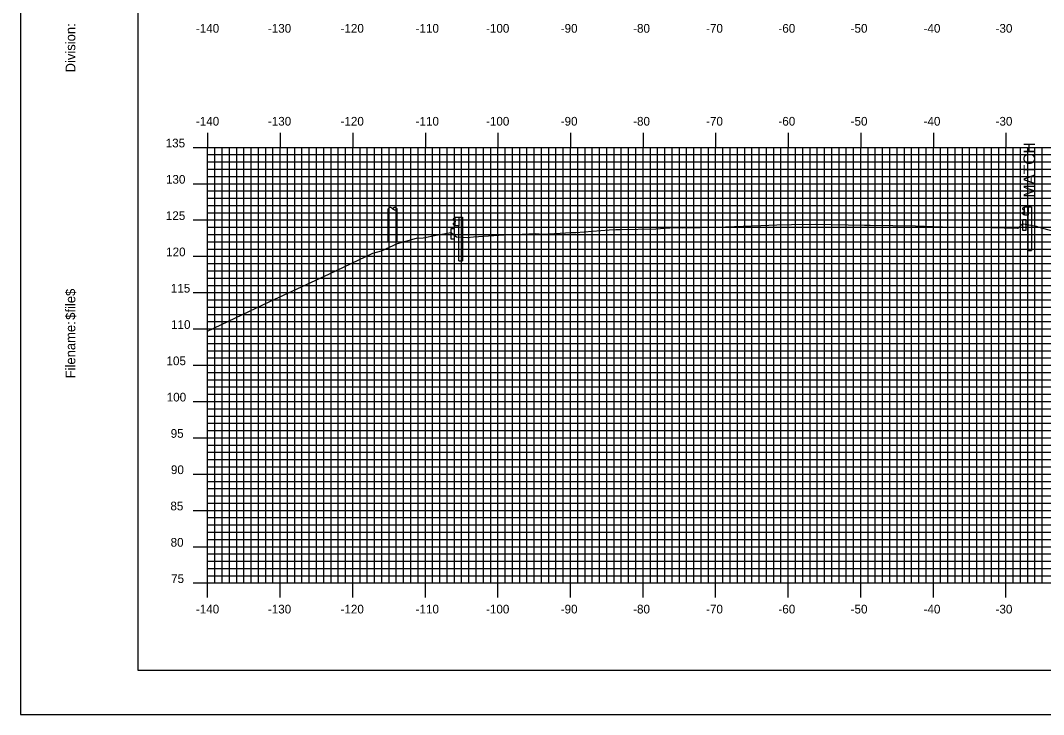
# Model space of a CAD drawing. Extents: x 857265 to 857608, y 364366 to 364586.
# Drawn here: x 857264.5 to 857405.5, y 364365.7 to 364461.3 of the extents above; entities that cross this region are included whole.
import ezdxf

# ---------------------------------------------------------------- set-up
doc = ezdxf.new("R2010")
doc.units = 0
for name, color, linetype in [('ANNOTATION', 7, 'Continuous'), ('BORDER', 7, 'Continuous'), ('H_V ANNOTATION', 7, 'Continuous'), ('M_Roadway_Centerline', 7, 'Continuous'), ('MAJOR', 7, 'Continuous'), ('MINOR', 7, 'Continuous'), ('PLOT BOUNDARY', 7, 'Continuous'), ('S_Curb_Type_1', 7, 'Continuous'), ('S_Guardrail_Beam', 7, 'Continuous'), ('S_Roadway_Centerline', 7, 'Continuous'), ('S_Utilities_Pole_Power', 7, 'Continuous')]:
    doc.layers.add(name, color=color, linetype=linetype)

msp = doc.modelspace()

# ---------------------------------------------------------------- linework, layer by layer
at = {"layer": 'BORDER'}
msp.add_lwpolyline([(857280.74, 364371.79), (857600.74, 364371.79), (857600.74, 364581.79), (857280.74, 364581.79)], close=True, dxfattribs=at)
at = {"layer": 'MAJOR'}
for p, q in [((857290.34, 364445.79), (857290.34, 364443.79)), ((857300.34, 364445.79), (857300.34, 364443.79)), ((857310.34, 364445.79), (857310.34, 364443.79)), ((857320.34, 364445.79), (857320.34, 364443.79)), ((857330.34, 364445.79), (857330.34, 364443.79)), ((857340.34, 364445.79), (857340.34, 364443.79)), ((857350.34, 364445.79), (857350.34, 364443.79)), ((857360.34, 364445.79), (857360.34, 364443.79)), ((857370.34, 364445.79), (857370.34, 364443.79)), ((857380.34, 364445.79), (857380.34, 364443.79)), ((857390.34, 364445.79), (857390.34, 364443.79)), ((857400.34, 364445.79), (857400.34, 364443.79)), ((857288.33, 364443.79), (857290.34, 364443.79)), ((857290.34, 364443.79), (857570.34, 364443.79)), ((857290.34, 364383.79), (857290.34, 364443.79)), ((857290.34, 364383.79), (857290.34, 364443.79)), ((857290.34, 364443.79), (857570.34, 364443.79)), ((857300.34, 364383.79), (857300.34, 364443.79)), ((857310.34, 364383.79), (857310.34, 364443.79)), ((857320.34, 364383.79), (857320.34, 364443.79)), ((857330.34, 364383.79), (857330.34, 364443.79)), ((857340.34, 364383.79), (857340.34, 364443.79)), ((857350.34, 364383.79), (857350.34, 364443.79)), ((857360.34, 364383.79), (857360.34, 364443.79)), ((857370.34, 364383.79), (857370.34, 364443.79)), ((857380.34, 364383.79), (857380.34, 364443.79)), ((857390.34, 364383.79), (857390.34, 364443.79)), ((857400.34, 364383.79), (857400.34, 364443.79)), ((857288.33, 364438.79), (857290.34, 364438.79)), ((857290.34, 364438.79), (857570.34, 364438.79)), ((857288.33, 364433.79), (857290.34, 364433.79)), ((857290.34, 364433.79), (857570.34, 364433.79)), ((857288.33, 364428.79), (857290.34, 364428.79)), ((857290.34, 364428.79), (857570.34, 364428.79)), ((857288.33, 364423.79), (857290.34, 364423.79)), ((857290.34, 364423.79), (857570.34, 364423.79)), ((857288.33, 364418.79), (857290.34, 364418.79)), ((857290.34, 364418.79), (857570.34, 364418.79)), ((857288.33, 364413.79), (857290.34, 364413.79)), ((857290.34, 364413.79), (857570.34, 364413.79)), ((857288.33, 364408.79), (857290.34, 364408.79)), ((857290.34, 364408.79), (857570.34, 364408.79)), ((857288.33, 364403.79), (857290.34, 364403.79)), ((857290.34, 364403.79), (857570.34, 364403.79)), ((857288.33, 364398.79), (857290.34, 364398.79)), ((857290.34, 364398.79), (857570.34, 364398.79)), ((857288.33, 364393.79), (857290.34, 364393.79)), ((857290.34, 364393.79), (857570.34, 364393.79)), ((857288.33, 364388.79), (857290.34, 364388.79)), ((857290.34, 364388.79), (857570.34, 364388.79)), ((857288.33, 364383.79), (857290.34, 364383.79)), ((857290.34, 364383.79), (857570.34, 364383.79)), ((857290.34, 364383.79), (857570.34, 364383.79)), ((857290.34, 364381.78), (857290.34, 364383.79)), ((857300.34, 364381.78), (857300.34, 364383.79)), ((857310.34, 364381.78), (857310.34, 364383.79)), ((857320.34, 364381.78), (857320.34, 364383.79)), ((857330.34, 364381.78), (857330.34, 364383.79)), ((857340.34, 364381.78), (857340.34, 364383.79)), ((857350.34, 364381.78), (857350.34, 364383.79)), ((857360.34, 364381.78), (857360.34, 364383.79)), ((857370.34, 364381.78), (857370.34, 364383.79)), ((857380.34, 364381.78), (857380.34, 364383.79)), ((857390.34, 364381.78), (857390.34, 364383.79)), ((857400.34, 364381.78), (857400.34, 364383.79))]:
    msp.add_line(p, q, dxfattribs=at)
at = {"layer": 'MINOR'}
for p, q in [((857291.34, 364383.79), (857291.34, 364443.79)), ((857292.34, 364383.79), (857292.34, 364443.79)), ((857293.34, 364383.79), (857293.34, 364443.79)), ((857294.34, 364383.79), (857294.34, 364443.79)), ((857295.34, 364383.79), (857295.34, 364443.79)), ((857296.34, 364383.79), (857296.34, 364443.79)), ((857297.34, 364383.79), (857297.34, 364443.79)), ((857298.34, 364383.79), (857298.34, 364443.79)), ((857299.34, 364383.79), (857299.34, 364443.79)), ((857301.34, 364383.79), (857301.34, 364443.79)), ((857302.34, 364383.79), (857302.34, 364443.79)), ((857303.34, 364383.79), (857303.34, 364443.79)), ((857304.34, 364383.79), (857304.34, 364443.79)), ((857305.34, 364383.79), (857305.34, 364443.79)), ((857306.34, 364383.79), (857306.34, 364443.79)), ((857307.34, 364383.79), (857307.34, 364443.79)), ((857308.34, 364383.79), (857308.34, 364443.79)), ((857309.34, 364383.79), (857309.34, 364443.79)), ((857311.34, 364383.79), (857311.34, 364443.79)), ((857312.34, 364383.79), (857312.34, 364443.79)), ((857313.34, 364383.79), (857313.34, 364443.79)), ((857314.34, 364383.79), (857314.34, 364443.79)), ((857315.34, 364383.79), (857315.34, 364443.79)), ((857316.34, 364383.79), (857316.34, 364443.79)), ((857317.34, 364383.79), (857317.34, 364443.79)), ((857318.34, 364383.79), (857318.34, 364443.79)), ((857319.34, 364383.79), (857319.34, 364443.79)), ((857321.34, 364383.79), (857321.34, 364443.79)), ((857322.34, 364383.79), (857322.34, 364443.79)), ((857323.34, 364383.79), (857323.34, 364443.79)), ((857324.34, 364383.79), (857324.34, 364443.79)), ((857325.34, 364383.79), (857325.34, 364443.79)), ((857326.34, 364383.79), (857326.34, 364443.79)), ((857327.34, 364383.79), (857327.34, 364443.79)), ((857328.34, 364383.79), (857328.34, 364443.79)), ((857329.34, 364383.79), (857329.34, 364443.79)), ((857331.34, 364383.79), (857331.34, 364443.79)), ((857332.34, 364383.79), (857332.34, 364443.79)), ((857333.34, 364383.79), (857333.34, 364443.79)), ((857334.34, 364383.79), (857334.34, 364443.79)), ((857335.34, 364383.79), (857335.34, 364443.79)), ((857336.34, 364383.79), (857336.34, 364443.79)), ((857337.34, 364383.79), (857337.34, 364443.79)), ((857338.34, 364383.79), (857338.34, 364443.79)), ((857339.34, 364383.79), (857339.34, 364443.79)), ((857341.34, 364383.79), (857341.34, 364443.79)), ((857342.34, 364383.79), (857342.34, 364443.79)), ((857343.34, 364383.79), (857343.34, 364443.79)), ((857344.34, 364383.79), (857344.34, 364443.79)), ((857345.34, 364383.79), (857345.34, 364443.79)), ((857346.34, 364383.79), (857346.34, 364443.79)), ((857347.34, 364383.79), (857347.34, 364443.79)), ((857348.34, 364383.79), (857348.34, 364443.79)), ((857349.34, 364383.79), (857349.34, 364443.79)), ((857351.34, 364383.79), (857351.34, 364443.79)), ((857352.34, 364383.79), (857352.34, 364443.79)), ((857353.34, 364383.79), (857353.34, 364443.79)), ((857354.34, 364383.79), (857354.34, 364443.79)), ((857355.34, 364383.79), (857355.34, 364443.79)), ((857356.34, 364383.79), (857356.34, 364443.79)), ((857357.34, 364383.79), (857357.34, 364443.79)), ((857358.34, 364383.79), (857358.34, 364443.79)), ((857359.34, 364383.79), (857359.34, 364443.79)), ((857361.34, 364383.79), (857361.34, 364443.79)), ((857362.34, 364383.79), (857362.34, 364443.79)), ((857363.34, 364383.79), (857363.34, 364443.79)), ((857364.34, 364383.79), (857364.34, 364443.79)), ((857365.34, 364383.79), (857365.34, 364443.79)), ((857366.34, 364383.79), (857366.34, 364443.79)), ((857367.34, 364383.79), (857367.34, 364443.79)), ((857368.34, 364383.79), (857368.34, 364443.79)), ((857369.34, 364383.79), (857369.34, 364443.79)), ((857371.34, 364383.79), (857371.34, 364443.79)), ((857372.34, 364383.79), (857372.34, 364443.79)), ((857373.34, 364383.79), (857373.34, 364443.79)), ((857374.34, 364383.79), (857374.34, 364443.79)), ((857375.34, 364383.79), (857375.34, 364443.79)), ((857376.34, 364383.79), (857376.34, 364443.79)), ((857377.34, 364383.79), (857377.34, 364443.79)), ((857378.34, 364383.79), (857378.34, 364443.79)), ((857379.34, 364383.79), (857379.34, 364443.79)), ((857381.34, 364383.79), (857381.34, 364443.79)), ((857382.34, 364383.79), (857382.34, 364443.79)), ((857383.34, 364383.79), (857383.34, 364443.79)), ((857384.34, 364383.79), (857384.34, 364443.79)), ((857385.34, 364383.79), (857385.34, 364443.79)), ((857386.34, 364383.79), (857386.34, 364443.79)), ((857387.34, 364383.79), (857387.34, 364443.79)), ((857388.34, 364383.79), (857388.34, 364443.79)), ((857389.34, 364383.79), (857389.34, 364443.79)), ((857391.34, 364383.79), (857391.34, 364443.79)), ((857392.34, 364383.79), (857392.34, 364443.79)), ((857393.34, 364383.79), (857393.34, 364443.79)), ((857394.34, 364383.79), (857394.34, 364443.79)), ((857395.34, 364383.79), (857395.34, 364443.79)), ((857396.34, 364383.79), (857396.34, 364443.79)), ((857397.34, 364383.79), (857397.34, 364443.79)), ((857398.34, 364383.79), (857398.34, 364443.79)), ((857399.34, 364383.79), (857399.34, 364443.79)), ((857401.34, 364383.79), (857401.34, 364443.79)), ((857402.34, 364383.79), (857402.34, 364443.79)), ((857403.34, 364383.79), (857403.34, 364443.79)), ((857404.34, 364383.79), (857404.34, 364443.79)), ((857405.34, 364383.79), (857405.34, 364443.79)), ((857290.34, 364442.79), (857570.34, 364442.79)), ((857290.34, 364442.79), (857292.34, 364442.79)), ((857290.34, 364441.79), (857570.34, 364441.79)), ((857290.34, 364441.79), (857292.34, 364441.79)), ((857290.34, 364440.79), (857570.34, 364440.79)), ((857290.34, 364440.79), (857292.34, 364440.79)), ((857290.34, 364439.79), (857570.34, 364439.79)), ((857290.34, 364439.79), (857292.34, 364439.79)), ((857290.34, 364437.79), (857570.34, 364437.79)), ((857290.34, 364437.79), (857292.34, 364437.79)), ((857290.34, 364436.79), (857570.34, 364436.79)), ((857290.34, 364436.79), (857292.34, 364436.79)), ((857290.34, 364435.79), (857570.34, 364435.79)), ((857290.34, 364435.79), (857292.34, 364435.79)), ((857290.34, 364434.79), (857570.34, 364434.79)), ((857290.34, 364434.79), (857292.34, 364434.79)), ((857290.34, 364432.79), (857570.34, 364432.79)), ((857290.34, 364432.79), (857292.34, 364432.79)), ((857290.34, 364431.79), (857570.34, 364431.79)), ((857290.34, 364431.79), (857292.34, 364431.79)), ((857290.34, 364430.79), (857570.34, 364430.79)), ((857290.34, 364430.79), (857292.34, 364430.79)), ((857290.34, 364429.79), (857570.34, 364429.79)), ((857290.34, 364429.79), (857292.34, 364429.79)), ((857290.34, 364427.79), (857570.34, 364427.79)), ((857290.34, 364427.79), (857292.34, 364427.79)), ((857290.34, 364426.79), (857570.34, 364426.79)), ((857290.34, 364426.79), (857292.34, 364426.79)), ((857290.34, 364425.79), (857570.34, 364425.79)), ((857290.34, 364425.79), (857292.34, 364425.79)), ((857290.34, 364424.79), (857570.34, 364424.79)), ((857290.34, 364424.79), (857292.34, 364424.79)), ((857290.34, 364422.79), (857570.34, 364422.79)), ((857290.34, 364422.79), (857292.34, 364422.79)), ((857290.34, 364421.79), (857570.34, 364421.79)), ((857290.34, 364421.79), (857292.34, 364421.79)), ((857290.34, 364420.79), (857570.34, 364420.79)), ((857290.34, 364420.79), (857292.34, 364420.79)), ((857290.34, 364419.79), (857570.34, 364419.79)), ((857290.34, 364419.79), (857292.34, 364419.79)), ((857290.34, 364417.79), (857570.34, 364417.79)), ((857290.34, 364417.79), (857292.34, 364417.79)), ((857290.34, 364416.79), (857570.34, 364416.79)), ((857290.34, 364416.79), (857292.34, 364416.79)), ((857290.34, 364415.79), (857570.34, 364415.79)), ((857290.34, 364415.79), (857292.34, 364415.79)), ((857290.34, 364414.79), (857570.34, 364414.79)), ((857290.34, 364414.79), (857292.34, 364414.79)), ((857290.34, 364412.79), (857570.34, 364412.79)), ((857290.34, 364412.79), (857292.34, 364412.79)), ((857290.34, 364411.79), (857570.34, 364411.79)), ((857290.34, 364411.79), (857292.34, 364411.79)), ((857290.34, 364410.79), (857570.34, 364410.79)), ((857290.34, 364410.79), (857292.34, 364410.79)), ((857290.34, 364409.79), (857570.34, 364409.79)), ((857290.34, 364409.79), (857292.34, 364409.79)), ((857290.34, 364407.79), (857570.34, 364407.79)), ((857290.34, 364407.79), (857292.34, 364407.79)), ((857290.34, 364406.79), (857570.34, 364406.79)), ((857290.34, 364406.79), (857292.34, 364406.79)), ((857290.34, 364405.79), (857570.34, 364405.79)), ((857290.34, 364405.79), (857292.34, 364405.79)), ((857290.34, 364404.79), (857570.34, 364404.79)), ((857290.34, 364404.79), (857292.34, 364404.79)), ((857290.34, 364402.79), (857570.34, 364402.79)), ((857290.34, 364402.79), (857292.34, 364402.79)), ((857290.34, 364401.79), (857570.34, 364401.79)), ((857290.34, 364401.79), (857292.34, 364401.79)), ((857290.34, 364400.79), (857570.34, 364400.79)), ((857290.34, 364400.79), (857292.34, 364400.79)), ((857290.34, 364399.79), (857570.34, 364399.79)), ((857290.34, 364399.79), (857292.34, 364399.79)), ((857290.34, 364397.79), (857570.34, 364397.79)), ((857290.34, 364397.79), (857292.34, 364397.79)), ((857290.34, 364396.79), (857570.34, 364396.79)), ((857290.34, 364396.79), (857292.34, 364396.79)), ((857290.34, 364395.79), (857570.34, 364395.79)), ((857290.34, 364395.79), (857292.34, 364395.79)), ((857290.34, 364394.79), (857570.34, 364394.79)), ((857290.34, 364394.79), (857292.34, 364394.79)), ((857290.34, 364392.79), (857570.34, 364392.79)), ((857290.34, 364392.79), (857292.34, 364392.79)), ((857290.34, 364391.79), (857570.34, 364391.79)), ((857290.34, 364391.79), (857292.34, 364391.79)), ((857290.34, 364390.79), (857570.34, 364390.79)), ((857290.34, 364390.79), (857292.34, 364390.79)), ((857290.34, 364389.79), (857570.34, 364389.79)), ((857290.34, 364389.79), (857292.34, 364389.79)), ((857290.34, 364387.79), (857570.34, 364387.79)), ((857290.34, 364387.79), (857292.34, 364387.79)), ((857290.34, 364386.79), (857570.34, 364386.79)), ((857290.34, 364386.79), (857292.34, 364386.79)), ((857290.34, 364385.79), (857570.34, 364385.79)), ((857290.34, 364385.79), (857292.34, 364385.79)), ((857290.34, 364384.79), (857570.34, 364384.79)), ((857290.34, 364384.79), (857292.34, 364384.79))]:
    msp.add_line(p, q, dxfattribs=at)
at = {"layer": 'PLOT BOUNDARY'}
msp.add_lwpolyline([(857264.55, 364365.67), (857604.55, 364365.67), (857604.55, 364585.67), (857264.55, 364585.67)], close=True, dxfattribs=at)
at = {"layer": 'S_Curb_Type_1'}
for points in [[(857402.67, 364433.86), (857403.09, 364433.86), (857403.09, 364432.36), (857402.67, 364432.36)], [(857402.67, 364433.86), (857403.09, 364433.86), (857403.09, 364432.36), (857402.67, 364432.36)], [(857323.89, 364432.63), (857324.31, 364432.63), (857324.31, 364431.13), (857323.89, 364431.13)], [(857323.89, 364432.63), (857324.31, 364432.63), (857324.31, 364431.13), (857323.89, 364431.13)]]:
    msp.add_lwpolyline(points, close=True, dxfattribs=at)
at = {"layer": 'S_Guardrail_Beam'}
for p, q in [((857402.79, 364435.52), (857402.65, 364435.42)), ((857402.79, 364435.52), (857402.65, 364435.42)), ((857402.65, 364435.28), (857402.84, 364435.14)), ((857402.65, 364435.28), (857402.84, 364435.14)), ((857402.84, 364434.92), (857402.65, 364434.78)), ((857402.84, 364434.92), (857402.65, 364434.78)), ((857402.89, 364435.54), (857402.81, 364435.53)), ((857402.89, 364435.54), (857402.81, 364435.53)), ((857402.88, 364435.07), (857402.88, 364434.98)), ((857402.88, 364435.07), (857402.88, 364434.98)), ((857402.89, 364435.61), (857403.38, 364435.61)), ((857402.89, 364434.45), (857402.89, 364435.61)), ((857402.89, 364435.61), (857403.38, 364435.61)), ((857402.89, 364434.45), (857402.89, 364435.61)), ((857403.38, 364435.61), (857403.87, 364435.61)), ((857403.38, 364435.61), (857403.38, 364434.45)), ((857403.38, 364435.61), (857403.87, 364435.61)), ((857403.38, 364435.61), (857403.38, 364434.45)), ((857403.87, 364435.61), (857403.87, 364429.61)), ((857403.87, 364435.61), (857403.87, 364429.61)), ((857324.36, 364434.07), (857324.22, 364433.97)), ((857324.36, 364434.07), (857324.22, 364433.97)), ((857324.22, 364433.83), (857324.42, 364433.69)), ((857324.22, 364433.83), (857324.42, 364433.69)), ((857324.42, 364433.47), (857324.22, 364433.33)), ((857324.42, 364433.47), (857324.22, 364433.33)), ((857324.46, 364434.09), (857324.38, 364434.08)), ((857324.46, 364434.09), (857324.38, 364434.08)), ((857324.45, 364433.63), (857324.45, 364433.54)), ((857324.45, 364433.63), (857324.45, 364433.54)), ((857324.46, 364434.16), (857324.95, 364434.16)), ((857324.46, 364433), (857324.46, 364434.16)), ((857324.46, 364434.16), (857324.95, 364434.16)), ((857324.46, 364433), (857324.46, 364434.16)), ((857324.95, 364434.16), (857325.44, 364434.16)), ((857324.95, 364434.16), (857324.95, 364433)), ((857324.95, 364434.16), (857325.44, 364434.16)), ((857324.95, 364434.16), (857324.95, 364433)), ((857325.44, 364434.16), (857325.44, 364428.16)), ((857325.44, 364434.16), (857325.44, 364428.16)), ((857402.65, 364434.64), (857402.79, 364434.54)), ((857402.65, 364434.64), (857402.79, 364434.54)), ((857402.81, 364434.53), (857402.89, 364434.52)), ((857402.81, 364434.53), (857402.89, 364434.52)), ((857403.38, 364434.45), (857402.89, 364434.45)), ((857403.38, 364434.45), (857402.89, 364434.45)), ((857403.38, 364429.61), (857403.38, 364434.45)), ((857403.38, 364429.61), (857403.38, 364434.45)), ((857324.22, 364433.19), (857324.36, 364433.09)), ((857324.22, 364433.19), (857324.36, 364433.09)), ((857324.38, 364433.08), (857324.46, 364433.07)), ((857324.38, 364433.08), (857324.46, 364433.07)), ((857324.95, 364433), (857324.46, 364433)), ((857324.95, 364433), (857324.46, 364433)), ((857324.95, 364428.16), (857324.95, 364433)), ((857324.95, 364428.16), (857324.95, 364433)), ((857403.38, 364429.61), (857403.87, 364429.61)), ((857403.38, 364429.61), (857403.87, 364429.61)), ((857324.95, 364428.16), (857325.44, 364428.16)), ((857324.95, 364428.16), (857325.44, 364428.16))]:
    msp.add_line(p, q, dxfattribs=at)
for centre, major_axis, start_param, end_param in [((857402.7, 364435.35), (-0.0877, 0), 5.323254, 7.243116), ((857402.7, 364435.35), (-0.0877, 0), 5.323254, 7.243116), ((857402.7, 364434.71), (-0.0877, 0), 5.323254, 7.243116), ((857402.7, 364434.71), (-0.0877, 0), 5.323254, 7.243116), ((857402.81, 364435.48), (-0.0417, 0), 4.886922, 5.323254), ((857402.81, 364435.48), (-0.0417, 0), 4.886922, 5.323254), ((857402.8, 364435.07), (0.0789, 0), 0, 0.959931), ((857402.8, 364435.07), (0.0789, 0), 0, 0.959931), ((857402.8, 364434.98), (0.0789, 0), 5.323254, 6.283185), ((857402.8, 364434.98), (0.0789, 0), 5.323254, 6.283185), ((857324.27, 364433.9), (-0.0877, 0), 5.323254, 7.243116), ((857324.27, 364433.9), (-0.0877, 0), 5.323254, 7.243116), ((857324.27, 364433.26), (-0.0877, 0), 5.323254, 7.243116), ((857324.27, 364433.26), (-0.0877, 0), 5.323254, 7.243116), ((857324.39, 364434.04), (-0.0417, 0), 4.886922, 5.323254), ((857324.39, 364434.04), (-0.0417, 0), 4.886922, 5.323254), ((857324.37, 364433.63), (0.0789, 0), 0, 0.959931), ((857324.37, 364433.63), (0.0789, 0), 0, 0.959931), ((857324.37, 364433.54), (0.0789, 0), 5.323254, 6.283185), ((857324.37, 364433.54), (0.0789, 0), 5.323254, 6.283185), ((857402.81, 364434.57), (-0.0417, 0), 0.959931, 1.396263), ((857402.81, 364434.57), (-0.0417, 0), 0.959931, 1.396263), ((857324.39, 364433.13), (-0.0417, 0), 0.959931, 1.396263), ((857324.39, 364433.13), (-0.0417, 0), 0.959931, 1.396263)]:
    msp.add_ellipse(centre, major_axis=major_axis, ratio=0.995501, start_param=start_param, end_param=end_param, dxfattribs=at)
at = {"layer": 'S_Roadway_Centerline'}
msp.add_lwpolyline([(857290.34, 364418.46), (857298.91, 364422.57), (857307.13, 364426.39), (857313.1, 364429.23), (857314.31, 364429.53), (857316.49, 364430.55), (857319.13, 364431.31), (857320.06, 364431.32), (857321.83, 364431.68), (857323.89, 364432.05), (857323.99, 364431.99), (857324.61, 364431.47), (857326.08, 364431.4), (857326.97, 364431.45), (857331.83, 364431.81), (857332.79, 364431.77), (857335.47, 364431.91), (857336.62, 364431.86), (857340.41, 364432.07), (857341.06, 364432.09), (857345.67, 364432.44), (857346.58, 364432.5), (857347.18, 364432.48), (857352.08, 364432.57), (857354.67, 364432.74), (857355.8, 364432.71), (857360.5, 364432.82), (857366.57, 364433.02), (857368.76, 364433.12), (857370.78, 364433.17), (857374.14, 364433.2), (857380.85, 364433.08), (857381.62, 364433.08), (857387.89, 364432.97), (857394.06, 364432.76), (857395.1, 364432.85), (857396.45, 364432.81), (857401.93, 364432.66), (857402.02, 364432.67), (857402.62, 364433.24), (857402.67, 364433.28), (857402.77, 364433.25), (857404.49, 364432.92), (857404.88, 364432.81), (857411.36, 364431.08)], dxfattribs=at)
at = {"layer": 'S_Utilities_Pole_Power'}
for p, q in [((857315.21, 364430.73), (857315.2, 364435.35)), ((857315.21, 364430.73), (857315.2, 364435.35)), ((857315.21, 364435.35), (857315.36, 364435.46)), ((857315.21, 364435.35), (857315.36, 364435.46)), ((857315.67, 364435.46), (857315.83, 364435.35)), ((857315.67, 364435.46), (857315.83, 364435.35)), ((857315.99, 364435.46), (857315.83, 364435.35)), ((857315.99, 364435.46), (857315.83, 364435.35)), ((857315.83, 364435.35), (857315.99, 364435.24)), ((857315.83, 364435.35), (857315.99, 364435.24)), ((857316.46, 364435.35), (857316.3, 364435.46)), ((857316.46, 364435.35), (857316.3, 364435.46)), ((857316.3, 364435.24), (857316.46, 364435.35)), ((857316.3, 364435.24), (857316.46, 364435.35)), ((857316.46, 364430.73), (857316.45, 364435.35)), ((857316.46, 364430.73), (857316.45, 364435.35))]:
    msp.add_line(p, q, dxfattribs=at)
for centre, start, end in [((857315.52, 364435.24), 90, 125.2644), ((857315.52, 364435.24), 90, 125.2644), ((857315.52, 364435.24), 54.7356, 90), ((857315.52, 364435.24), 54.7356, 90), ((857316.14, 364435.24), 90, 125.2644), ((857316.14, 364435.24), 90, 125.2644), ((857316.14, 364435.46), 234.7356, 270), ((857316.14, 364435.46), 234.7356, 270), ((857316.14, 364435.24), 54.7356, 90), ((857316.14, 364435.24), 54.7356, 90), ((857316.14, 364435.46), 270, 305.2644), ((857316.14, 364435.46), 270, 305.2644)]:
    msp.add_arc(centre, 0.271, start, end, dxfattribs=at)

# ---------------------------------------------------------------- texts
at = {"layer": 'ANNOTATION'}
msp.add_text('MATCH', height=1.6, rotation=90, dxfattribs=at).set_placement((857404.36, 364436.89))
at = {"layer": 'BORDER'}
for s, p in [('Division:', (857272.11, 364454.12)), ('$file$', (857272.11, 364420.04)), ('Filename:', (857272.11, 364411.98))]:
    msp.add_text(s, height=1.339, rotation=90, dxfattribs=at).set_placement(p)
at = {"layer": 'H_V ANNOTATION'}
for s, p in [('-140', (857288.72, 364459.59)), ('-130', (857298.64, 364459.59)), ('-120', (857308.65, 364459.59)), ('-110', (857319, 364459.59)), ('-100', (857328.7, 364459.59)), ('-90', (857338.99, 364459.59)), ('-80', (857348.97, 364459.59)), ('-70', (857359.02, 364459.59)), ('-60', (857368.99, 364459.59)), ('-50', (857378.94, 364459.59)), ('-40', (857388.99, 364459.59)), ('-30', (857398.91, 364459.59)), ('-140', (857288.72, 364446.79)), ('-130', (857298.64, 364446.79)), ('-120', (857308.65, 364446.79)), ('-110', (857319, 364446.79)), ('-100', (857328.7, 364446.79)), ('-90', (857338.99, 364446.79)), ('-80', (857348.97, 364446.79)), ('-70', (857359.02, 364446.79)), ('-60', (857368.99, 364446.79)), ('-50', (857378.94, 364446.79)), ('-40', (857388.99, 364446.79)), ('-30', (857398.91, 364446.79)), ('135', (857284.56, 364443.79)), ('130', (857284.6, 364438.79)), ('125', (857284.58, 364433.79)), ('120', (857284.62, 364428.79)), ('115', (857285.27, 364423.79)), ('110', (857285.3, 364418.79)), ('105', (857284.67, 364413.79)), ('100', (857284.7, 364408.79)), ('95', (857285.25, 364403.79)), ('90', (857285.28, 364398.79)), ('85', (857285.21, 364393.79)), ('80', (857285.24, 364388.79)), ('75', (857285.31, 364383.79)), ('-140', (857288.72, 364379.59)), ('-130', (857298.64, 364379.59)), ('-120', (857308.65, 364379.59)), ('-110', (857319, 364379.59)), ('-100', (857328.7, 364379.59)), ('-90', (857338.99, 364379.59)), ('-80', (857348.97, 364379.59)), ('-70', (857359.02, 364379.59)), ('-60', (857368.99, 364379.59)), ('-50', (857378.94, 364379.59)), ('-40', (857388.99, 364379.59)), ('-30', (857398.91, 364379.59))]:
    msp.add_text(s, height=1.2, dxfattribs=at).set_placement(p)
at = {"layer": 'M_Roadway_Centerline'}
for s, p in [('C', (857340.4, 364432.07)), ('L', (857340.41, 364432.07)), ('C', (857374.14, 364433.2)), ('L', (857374.14, 364433.19))]:
    msp.add_text(s, height=0.0146, dxfattribs=at).set_placement(p)
at = {"layer": 'MAJOR'}
msp.add_text('-', height=0.012, dxfattribs=at).set_placement((857290.33, 364383.79))

doc.saveas('drawing.dxf')
